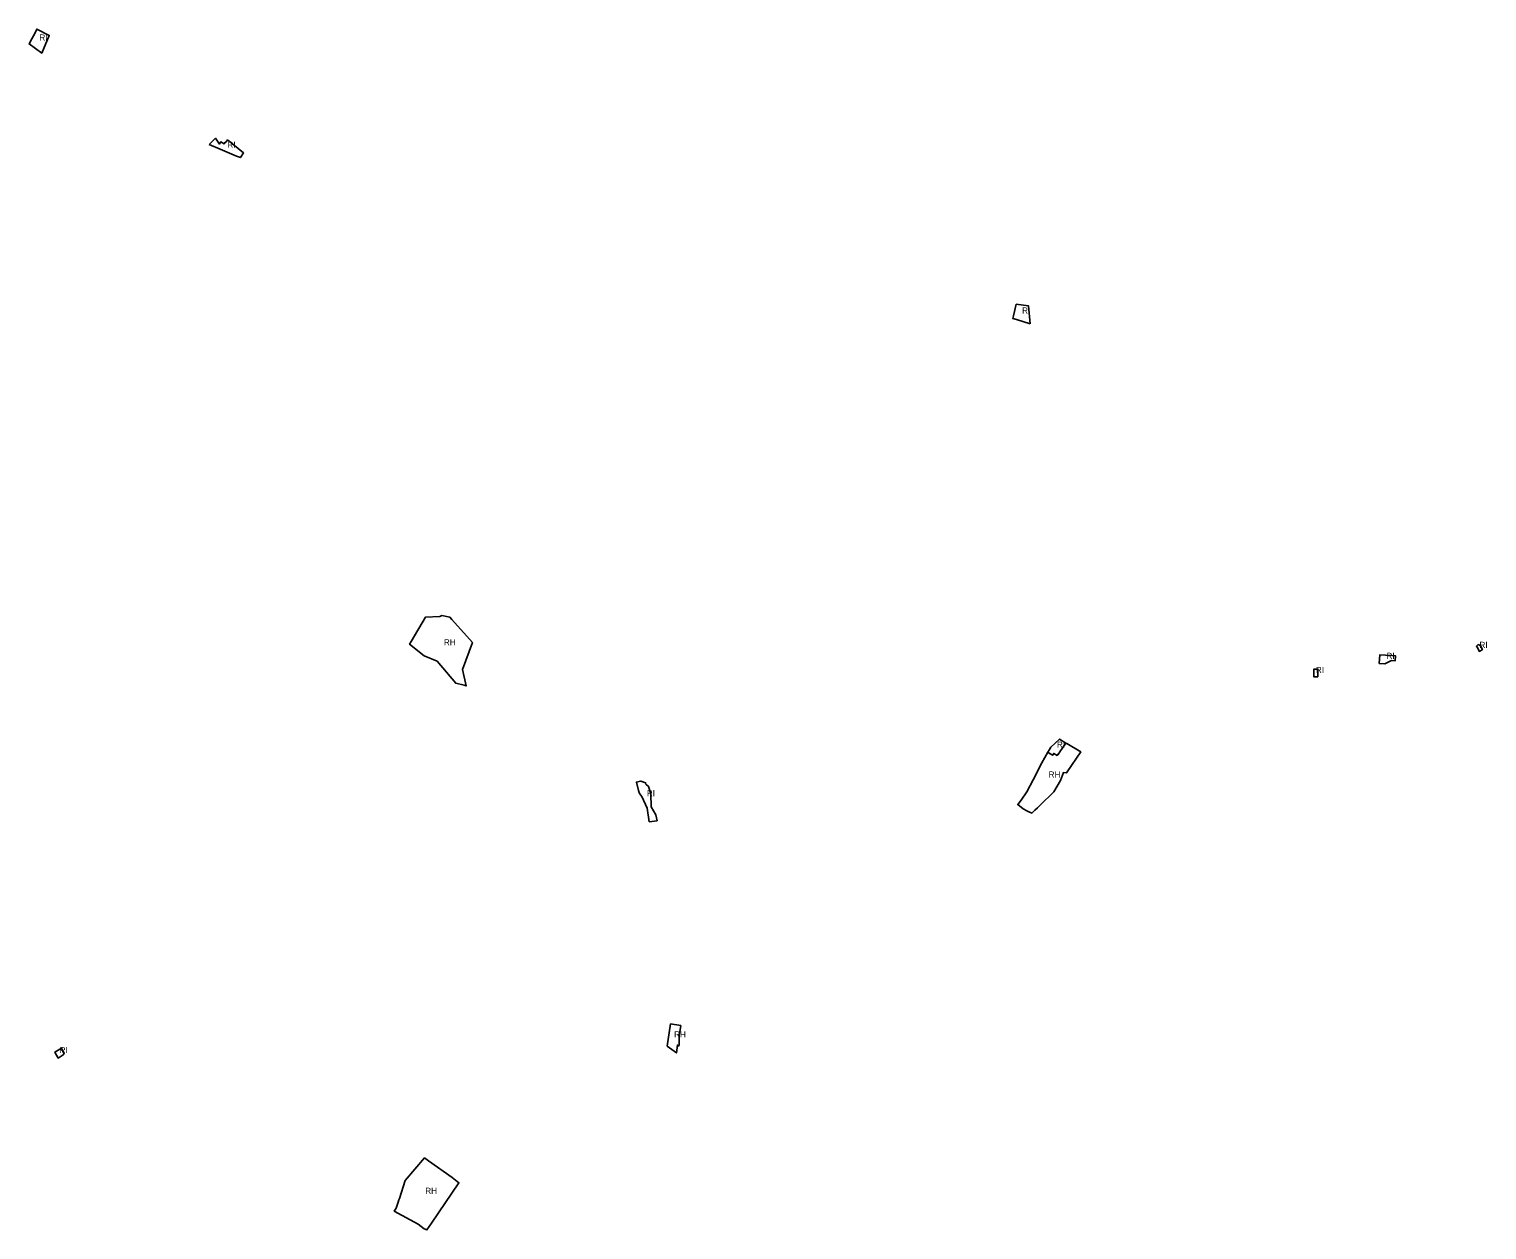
# Model space of a CAD drawing. Extents: x -477010 to -466219, y -1158799 to -1150161.
# Drawn here: x -474010 to -471852, y -1152491 to -1150713 of the extents above; entities that cross this region are included whole.
import ezdxf

# ---------------------------------------------------------------- set-up
doc = ezdxf.new("R2010")
doc.units = 0
doc.layers.add('16', color=7, linetype='Continuous')
doc.layers.add('19', color=7, linetype='Continuous')

msp = doc.modelspace()

# ---------------------------------------------------------------- linework, layer by layer
at = {"layer": '16'}
for points in [[(-473366.04, -1151684.3), (-473378.42, -1151681.276), (-473406.002, -1151648.406), (-473425.306, -1151640.423), (-473446.649, -1151623.586), (-473444.3, -1151619.58), (-473422.98, -1151583.22), (-473402.03, -1151582.51), (-473399.13, -1151580.98), (-473386.97, -1151583.52), (-473384.22, -1151586.61), (-473353.7, -1151620.82), (-473368.3, -1151660.79), (-473362.85, -1151685.08)], [(-472475.11, -1151769.78), (-472473.71, -1151770.61), (-472453.08, -1151782.85), (-472473.33, -1151812.58), (-472473.99, -1151813.92), (-472478.68, -1151813.41), (-472483.2, -1151825.45), (-472492.72, -1151841.97), (-472513.29, -1151861.75), (-472517.16, -1151865.47), (-472520.87, -1151869.04), (-472525.55, -1151873.53), (-472530.66, -1151870.94), (-472532.68, -1151869.92), (-472538.48, -1151866.98), (-472546.24, -1151860.836), (-472541.24, -1151854.28), (-472532.9, -1151841.89), (-472523.2, -1151824.34), (-472510.7, -1151799.03), (-472501.72, -1151783.43), (-472498.24, -1151785.53), (-472494.501, -1151787.786), (-472492.89, -1151785.13), (-472488.13, -1151788), (-472487.12, -1151786.33), (-472486.26, -1151786.85), (-472483.82, -1151782.8)], [(-473065.29, -1152218.57), (-473060.12, -1152185.69), (-473045.29, -1152188.16), (-473046.24, -1152194.19), (-473047.54, -1152202.49), (-473047.37, -1152216.42), (-473048.19, -1152218.51), (-473050.13, -1152216.93), (-473051.6, -1152228.45)], [(-473462.92, -1152447.83), (-473463.3, -1152447.55), (-473462.4, -1152446.27), (-473461.68, -1152444.13), (-473453.2, -1152417.27), (-473424.48, -1152383.96), (-473418.41, -1152388.5), (-473383.58, -1152413.12), (-473373.66, -1152420.69), (-473414.23, -1152480.56), (-473420.99, -1152490.54), (-473425.1, -1152489.27), (-473434.06, -1152482), (-473469.41, -1152462.84), (-473466.41, -1152458.3)]]:
    msp.add_lwpolyline(points, close=True, dxfattribs=at)
at = {"layer": '19'}
for points in [[(-474006.02, -1150727.26), (-474001.17, -1150718.1), (-473998.33, -1150712.74), (-473980.085, -1150721.934), (-473991.204, -1150748.057), (-474009.88, -1150734.54)], [(-473743.451, -1150883.735), (-473734.01, -1150874.24), (-473728.3, -1150882.91), (-473726.87, -1150880.92), (-473725.87, -1150879.51), (-473721.32, -1150882.77), (-473719.63, -1150880.1), (-473719.1, -1150880.51), (-473716.03, -1150876.71), (-473692.35, -1150896.07), (-473697.05, -1150902.98), (-473702.68, -1150900.64), (-473727.16, -1150890.49)], [(-472528.07, -1151149.09), (-472548.15, -1151142.45), (-472553.67, -1151140.94), (-472552.73, -1151137.19), (-472548.48, -1151120.06), (-472530.485, -1151122.362)], [(-471860.77, -1151626.92), (-471858.2, -1151631.39), (-471862.8, -1151634.03), (-471866.3, -1151627.93), (-471867.14, -1151626.47), (-471864.46, -1151624.06), (-471861.7, -1151625.29)], [(-472003, -1151652.53), (-472011.05, -1151651.92), (-472010.07, -1151638.93), (-472002.02, -1151639.54), (-471992.6, -1151640.25), (-471986.77, -1151640.69), (-471987.31, -1151647.89), (-471993.15, -1151647.45)], [(-472102, -1151671.8), (-472108.03, -1151671.68), (-472107.94, -1151667.1), (-472107.8, -1151660.24), (-472103.51, -1151660.33), (-472101.77, -1151660.36)], [(-472497.23, -1151775.62), (-472484.3, -1151763.85), (-472475.11, -1151769.78), (-472483.82, -1151782.8), (-472486.26, -1151786.85), (-472487.12, -1151786.33), (-472488.13, -1151788), (-472492.89, -1151785.13), (-472494.501, -1151787.786), (-472498.24, -1151785.53), (-472501.72, -1151783.43), (-472499.3, -1151779.23)], [(-473106.51, -1151826.66), (-473104.63, -1151826.25), (-473104.38, -1151826.33), (-473097.28, -1151828.61), (-473097.01, -1151830.64), (-473092.93, -1151833.9), (-473089.32, -1151844.78), (-473089.22, -1151864.32), (-473081.84, -1151875.81), (-473080.13, -1151884.73), (-473091.84, -1151886.31), (-473094.96, -1151866.1), (-473102.96, -1151848.87), (-473106.43, -1151844.48), (-473107.63, -1151839.82), (-473110.75, -1151827.67)], [(-473957.98, -1152230.4), (-473966.86, -1152236.29), (-473971.76, -1152227.4), (-473962.07, -1152221.63)]]:
    msp.add_lwpolyline(points, close=True, dxfattribs=at)

# ---------------------------------------------------------------- texts
at = {"layer": '16'}
for p in [(-473395.7825, -1151625.034), (-472500.5375, -1151820.866), (-473055.0245, -1152205.519), (-473423.4055, -1152437.222)]:
    msp.add_text('RH', height=9, dxfattribs=at).set_placement(p)
at = {"layer": '19'}
for p in [(-473994.706, -1150729.644), (-473716.195, -1150888.443), (-472539.828, -1151133.832), (-472000.291, -1151645.168), (-471862.685, -1151628.893), (-472104.836, -1151666.016), (-472488.205, -1151776.587), (-473095.375, -1151848.474), (-473964.667, -1152228.906)]:
    msp.add_text('RI', height=9, dxfattribs=at).set_placement(p)

doc.saveas('drawing.dxf')
